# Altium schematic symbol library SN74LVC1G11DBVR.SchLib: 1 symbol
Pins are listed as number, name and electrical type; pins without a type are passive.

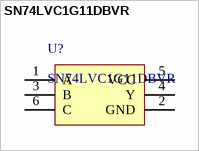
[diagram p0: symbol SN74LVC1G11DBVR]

## SN74LVC1G11DBVR
designator U?
1-ch, 3-input 1.65-V to 5.5-V 32 mA drive strength AND gate 6-SOT-23 -40 to 125; Manufacturer_Name: Texas Instruments; CompType: IC
footprint DBV0006A_L
pins: 1 A, 2 GND, 3 B, 4 Y, 5 VCC, 6 C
